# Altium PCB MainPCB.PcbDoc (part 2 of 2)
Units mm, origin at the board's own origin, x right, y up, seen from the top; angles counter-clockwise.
Board outline 105.16 x 70.61 mm, 2 copper layers (Top Layer, Bottom Layer); 130 components, 114 nets, 556 pads, 141 vias.
Unrouted connection lines stored in the file: 1.
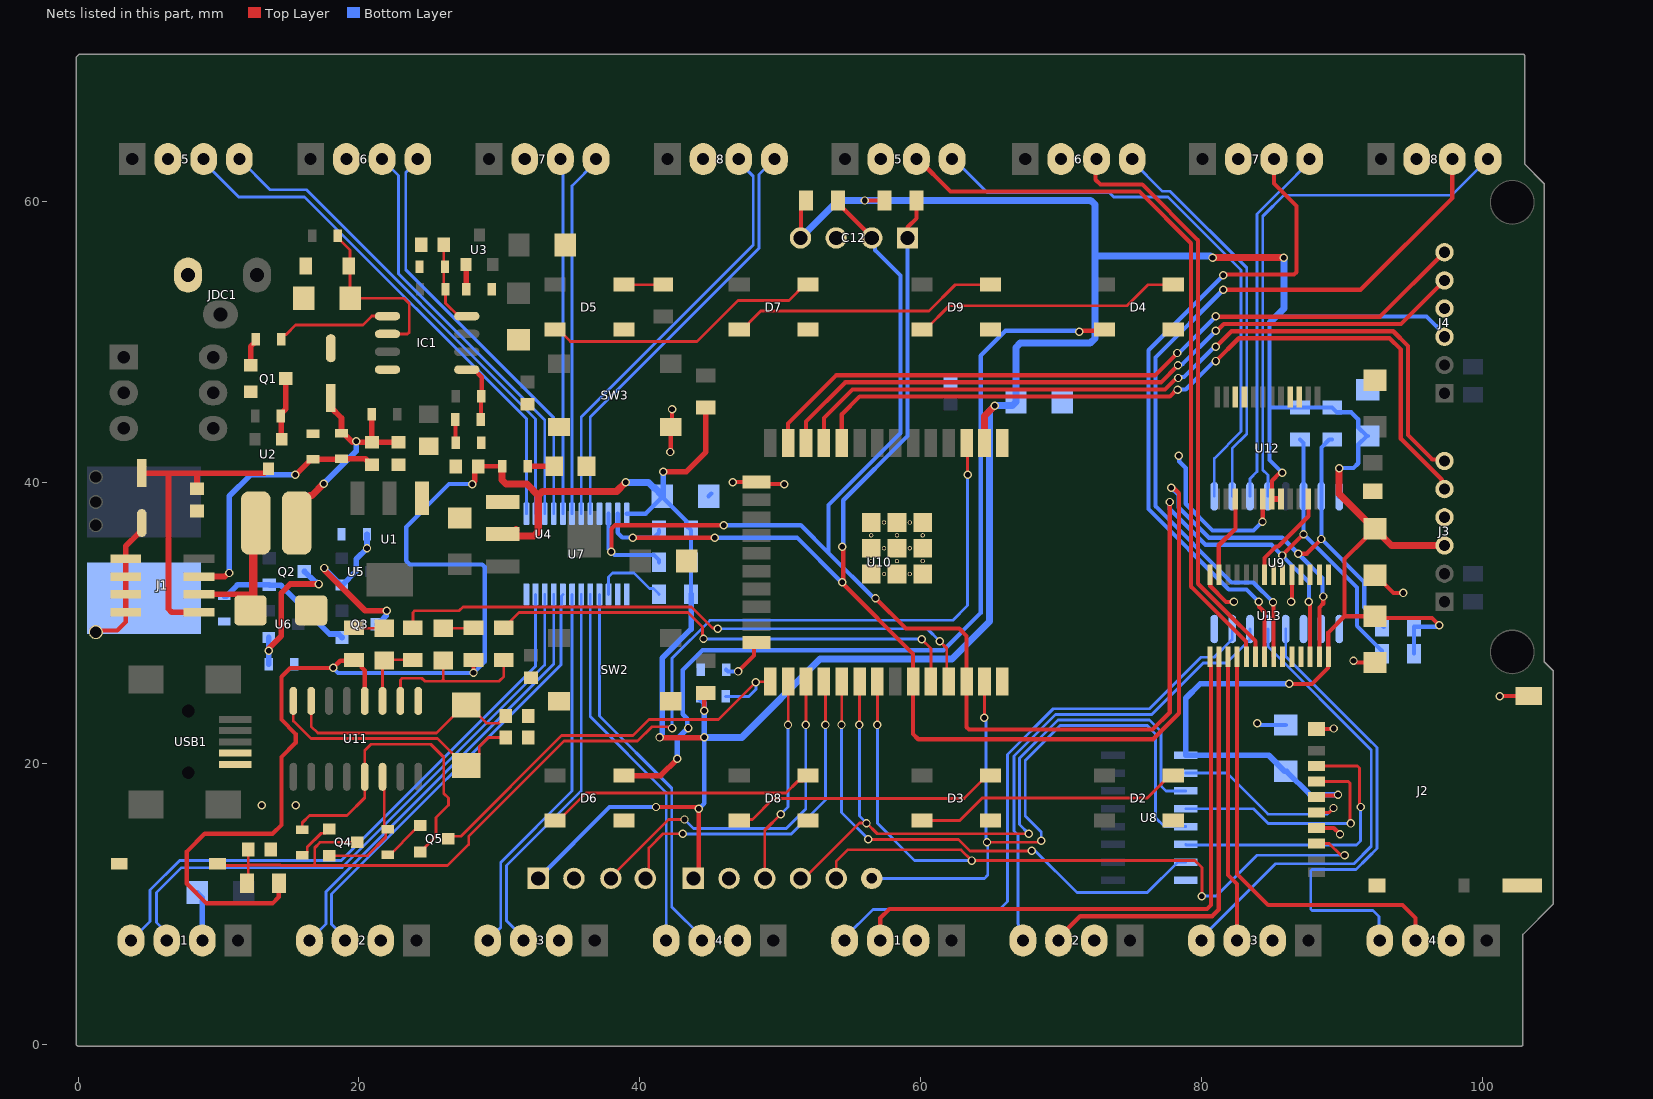
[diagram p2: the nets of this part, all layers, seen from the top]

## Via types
v1: diameter 0.6, hole 0.4, Top Layer to Bottom Layer, tented both sides, 141 vias

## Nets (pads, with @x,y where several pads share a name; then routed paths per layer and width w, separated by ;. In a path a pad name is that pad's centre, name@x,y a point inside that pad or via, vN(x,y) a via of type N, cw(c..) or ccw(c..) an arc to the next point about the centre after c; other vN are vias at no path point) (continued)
DTR_CH340: Q5.2 R29.1 U11.13 | length 23
  Top Layer w0.2: R29.1@15.965,15.266 15.965,15.774 16.473,16.282 19.14,16.282 20.41,17.552 U11.13@20.41,19.043 20.41,20.918 20.854,21.362 25.109,21.362 26.035,20.436 26.035,17.867 26.381,17.521 26.381,17.023 25.49,16.132 25.49,14.808 24.713,14.031 24.713,13.981 24.413,13.681 Q5.2@24.363,13.681
EN: Cx9.2 Q4.3 R28.1 SW4.1 U10.3 | length 83
  Top Layer w0.2: SW4.1@9.94,12.853 10.067,12.726 12.117,12.726 ; R28.1@12.028,11.456 12.117,11.545 12.117,12.774 ; Cx9.2@12.117,13.869 12.117,12.774 ; Q4.3@19.886,14.377 17.235,14.377 16.854,13.996 16.854,12.843 16.737,12.726 ; v1(42.291,22.514) 42.214,22.591 41.989,22.591 41.974,22.606 40.859,22.606 39.835,21.582 34.594,21.582 27.813,14.801 27.813,14.224 26.315,12.726 16.737,12.726 ; U10.3@63.262,42.816 63.336,42.742 v1(63.336,40.539) ; 12.117,12.774 14.403,12.774 14.451,12.726 16.737,12.726
  Bottom Layer w0.2: v1(42.291,22.514) 42.291,27.487 44.986,30.182 62.273,30.182 63.336,31.245 v1(63.336,40.539)
EN_POWER_BAT: IC1.1 R1.2 | length 8.3
  Top Layer w0.2: R1.2@14.479,50.191 14.479,50.341 14.679,50.541 14.829,50.541 15.495,51.207 20.283,51.207 20.918,51.842 IC1.1@22.03,51.842
GND: 1.2 2.2 3.2 4.2 5.2 6.2 7.2 8.2 -.1 BZT?.1 C1.1 C2.2 C3.2 C4.2 C5.2 C6.2 C7.2 C8.2 C9.1 C10.1 C11.1 C12.3 C13.1 C14.2 C15.2 C16.1 C17.2 C18.1 C19.1 Cx2.1 Cx3.1 Cx4.1 Cx5.1 Cx6.1 Cx7.1 Cx8.1 Cx9.1 Cx10.1 D1.A D2.3 D3.3 D4.3 D5.3 D6.3 D7.3 D8.3 D9.3 IC1.4 J1.5 J1.6 J1.7 J1.8 J2.6 J2.P1 J2.P2 J2.P3 J2.P4 J3.4 J4.4 JDC1.2 LED1.2 pad.5 pad.10 pad.17 Q1.1 R3.1 R7.1 R8.1 R9.1 R10.1 R12.2 R16.2 R27.1 SW2.1 SW2.4 SW3.1 SW3.4 SW4.2 U1.1 U4.1 U7.1 U7.2 U7.12 U7.21 U8.8 U9.1 U9.2 U9.3 U9.8 U10.1 U10.15 U10.38 U10.39_1 U10.39_2 U10.39_3 U10.39_4 U10.39_5 U10.39_6 U10.39_7 U10.39_8 U10.39_9 U10.39_10 U10.39_11 U10.39_12 U10.39_13 U10.39_14 U10.39_15 U10.39_16 U10.39_17 U10.39_18 U10.39_19 U10.39_20 U10.39_21 U11.1 U12.3 U12.4 U12.9 U12.10 U12.18 U13.1 U13.2 U13.3 U13.4 U13.5 U13.14 U13.23 U13.24 U13.25 USB1.4 USB1.5 | length 49.4
  Top Layer w0.3: pad.17@1.27,29.337 1.397,29.464 2.794,29.464 3.399,30.069 J1.8@3.399,30.76 ; v1(42.164,42.164) 42.202,42.202 SW3.1@42.202,43.942 42.291,44.031 v1(42.291,45.212) ; v1(46.609,40.005) 46.635,40.031 U10.15@48.292,40.031 48.445,39.878 v1(50.292,39.878) ; U13.14@80.583,33.427 80.61,33.399 80.61,32.625 81.739,31.496 v1(82.296,31.496) ; v1(84.328,37.211) 84.347,37.23 U12.18@84.347,38.819 ; v1(86.36,31.496) 86.425,31.561 U13.5@86.425,33.427 ; J2.6@88.179,15.403 89.404,15.403 v1(89.848,14.959) ; J2.P4@88.179,22.453 89.382,22.453 v1(89.408,22.479) ; v1(90.805,27.305) 90.932,27.178 C18.1@92.329,27.178 ; C16.1@92.329,33.401 92.392,33.401 93.662,32.131 v1(94.361,32.131) ; v1(101.219,24.765) 101.257,24.803 J2.P3@103.279,24.803
  Top Layer w0.4: J1.8@3.399,30.76 J1.7@3.399,32.03 J1.6@3.399,33.3 J1.5@3.399,34.57 3.399,35.47 4.332,36.403 4.396,36.403 4.535,36.541 C3.2@4.535,37.11
  Top Layer w0.6: U1.1@24.488,38.867 U1.1@24.488,39.567
  Bottom Layer w0.3: C11.1@44.896,39.015 C11.1@45.085,39.204 ; v1(78.359,41.91) 78.399,41.87 78.399,41.489 78.867,41.021 78.867,38.481 80.772,36.576 83.693,36.576 v1(84.328,37.211) ; v1(83.947,22.86) 84.074,22.733 C9.1@85.979,22.733
  Bottom Layer w0.4: C5.2@8.484,10.795 8.853,10.426 1.2@8.853,7.392
  other v1: 13.081,17.018 15.494,17.018
GPIO_0: Q5.3 R26.1 U10.25 | length 30.4
  Top Layer w0.2: Q5.3@26.363,14.631 26.536,14.804 27.25,14.804 34.428,21.982 39.508,21.982 40.64,23.114 45.593,23.114 v1(48.26,25.781) ; v1@48.26,25.816 U10.25@49.292,25.816
  Bottom Layer w0.2: R26.1@46.101,24.765 47.752,24.765 48.26,25.273 v1(48.26,25.781)
GPIO_2: R27.2 U10.24 | length 3.5
  Top Layer w0.3: v1(46.99,26.543) 48.133,27.686 48.133,28.442 U10.24@48.292,28.601
  Bottom Layer w0.3: R27.2@46.139,26.67 46.266,26.543 v1(46.99,26.543)
HAL_CHA_M1: J3.5 U10.10 | length 55.5
  Top Layer w0.3: U10.10@54.372,42.816 54.372,44.847 55.65,46.125 77.73,46.125 78.199,46.594 v1(78.28,46.594) ; v1(81.011,48.641) 82.636,50.266 93.371,50.266 94.177,49.46 94.177,43.11 97.089,40.198 97.089,39.716 J3.5@97.282,39.523
  Bottom Layer w0.3: v1(78.28,46.594) 78.295,46.609 78.867,46.609 v1@80.899,48.641
HAL_CHA_M2: J4.5 U10.12 | length 51.1
  Top Layer w0.3: U10.12@51.832,42.816 51.832,44.339 54.618,47.125 77.097,47.125 v1(78.312,48.34) ; v1(81.011,50.8) 81.092,50.8 81.574,51.282 94.183,51.282 J4.5@97.282,54.381
  Bottom Layer w0.3: v1(78.312,48.34) 78.37,48.398 78.608,48.398 v1(81.011,50.8)
HAL_CHB_M1: J3.6 U10.11 | length 56.1
  Top Layer w0.3: U10.11@53.102,42.816 53.102,44.593 55.134,46.625 77.392,46.625 78.203,47.436 v1(78.327,47.436) ; v1(81.011,49.657) 82.12,50.766 93.633,50.766 94.677,49.722 94.677,43.372 96.42,41.629 97.182,41.629 J3.6@97.282,41.529
  Bottom Layer w0.3: v1@78.265,47.498 78.74,47.498 80.749,49.507 80.78,49.507 80.899,49.626 v1@80.899,49.657 ; v1@78.27,47.493 v1(78.327,47.436)
HAL_CHB_M2: J4.6 U10.13 | length 53.2
  Top Layer w0.3: U10.13@50.562,42.816 50.546,42.832 50.546,44.196 53.975,47.625 76.678,47.625 v1(78.265,49.213) ; v1(81.011,51.831) 81.041,51.801 92.696,51.801 J4.6@97.282,56.387
  Bottom Layer w0.3: v1(78.265,49.213) 78.392,49.213 v1(81.011,51.831)
MCU_RX: R34.1 U10.34 | length 34.7
  Top Layer w0.2: R34.1@30.316,29.655 31.395,30.734 43.434,30.734 44.45,29.718 44.45,28.956 v1(44.529,28.877) ; v1(60.071,28.829) 60.071,28.816 60.722,28.165 U10.34@60.722,25.816
  Bottom Layer w0.2: v1(44.529,28.877) 44.553,28.853 60.047,28.853 v1(60.071,28.829)
MCU_TX: R33.1 U10.35 | length 42.9
  Top Layer w0.2: R33.1@23.839,29.655 23.839,30.744 23.956,30.861 27.13,30.861 27.403,31.134 43.669,31.134 45.164,29.639 45.499,29.639 v1(45.556,29.582) ; v1(61.341,28.702) 61.849,28.194 61.849,25.959 U10.35@61.992,25.816
  Bottom Layer w0.2: v1(45.556,29.582) 60.461,29.582 v1(61.341,28.702)
NetBZT?_2: BZT?.2 C8.1 IC1.2 R15.1 | length 12.8
  Top Layer w0.2: R15.1@18.505,57.557 18.505,57.407 19.369,56.544 C8.1@19.369,53.112 23.204,53.112 23.585,52.731 23.585,50.689 23.468,50.572 IC1.2@22.03,50.572
NetC3_1: C3.1 Cx3.2 J1.1 U2.3 | length 22.3
  Top Layer w0.4: C3.1@4.535,40.666 6.44,40.666 ; Cx3.2@8.472,39.561 8.472,40.539 8.599,40.666 ; J1.1@8.599,30.76 6.674,30.76 6.44,30.994 6.44,40.666 ; U2.3@13.552,40.963 13.552,40.913 13.352,40.713 13.302,40.713 13.255,40.666 8.599,40.666 ; 6.44,40.666 8.599,40.666
NetC4_1: C4.1 Cx1.1 Cx2.2 L1.2 R4.2 R5.1 | length 16.6
  Top Layer w0.4: C4.1@17.997,46 17.997,45.35 18.759,44.588 R4.2@18.759,43.498 18.909,43.498 v1@19.544,42.863 ; v1@19.812,42.863 Cx1.1@20.918,42.863 ; R5.1@20.918,44.857 Cx1.1@20.918,42.863 ; Cx2.2@22.823,42.863 Cx1.1@20.918,42.863
  Top Layer w0.5: L1.2@15.563,37.11 15.563,38.161 16.472,39.071 16.656,39.071 v1(17.489,39.904)
  Bottom Layer w0.4: v1(17.489,39.904) 19.812,42.227 v1(19.812,42.926)
NetCx1_2: Cx1.2 J1.3 R3.2 R4.1 | length 19.2
  Top Layer w0.4: J1.3@8.599,33.3 10.45,33.3 10.704,33.554 v1(10.758,33.554) ; v1(15.457,40.539) 15.472,40.539 16.577,41.644 R3.2@16.727,41.644 16.746,41.663 18.74,41.663 R4.1@18.759,41.682 20.449,41.682 20.868,41.263 Cx1.2@20.918,41.263
  Bottom Layer w0.4: v1(10.758,33.554) 10.758,39.015 12.282,40.539 v1(15.457,40.539)
NetCx5_2: Cx5.2 IC1.8 R11.2 R12.1 | length 6.1
  Top Layer w0.2: Cx5.2@26.036,56.922 26.036,55.353 26.036,53.874 R11.2@26.163,53.747 26.163,52.759 27.08,51.842 IC1.8@27.68,51.842
NetD1_C: D1.C J1.2 L1.1 | length 10.3
  Top Layer w0.4: J1.2@8.599,32.03 12.371,32.03 12.472,32.131
  Top Layer w0.6: D1.C@12.281,30.887 12.472,31.078 12.472,32.131 12.472,36.919 L1.1@12.663,37.11
NetD5_4: D5.4 R37.2 | length 2.8
  Top Layer w0.2: D5.4@38.862,54.076 41.63,54.076 R37.2@41.656,54.102
NetIC1_5: IC1.5 R13.2 R14.1 | length 4.3
  Top Layer w0.3: IC1.5@27.68,48.032 28.199,48.032 28.743,47.488 28.743,46.168 R13.2@28.703,46.127 28.684,46.108 28.684,44.495 R14.1@28.665,44.476
NetLabel438: U13.6
NetLabel439: U13.7
NetLED1_1: LED1.1 R6.1 | length 1.9
  Top Layer w0.4: R6.1@32.004,41.148 LED1.1@33.909,41.148
NetLED2_1: LD2.1 R30.1 | length 2.2
  Top Layer w0.2: R30.1@19.648,29.655 19.686,29.617 LD2.1@21.807,29.617
NetLED3_1: LD3.1 R31.1 | length 2.2
  Top Layer w0.2: LD3.1@25.998,29.617 28.119,29.617 R31.1@28.157,29.655
NetQ1_2: Q1.2 R2.1 U2.1 | length 4.5
  Top Layer w0.4: U2.1@14.502,43.063 14.472,43.093 14.472,44.7 R2.1@14.441,44.73 14.441,44.88 14.787,45.226 Q1.2@14.787,47.397
NetQ1_3: Q1.3 R1.1 | length 2
  Top Layer w0.4: Q1.3@12.287,48.347 12.287,49.665 12.663,50.041 R1.1@12.663,50.191
NetQ4_1: Q4.1 R29.2 | length 2.9
  Top Layer w0.2: R29.2@15.965,13.45 16.115,13.45 16.315,13.65 16.315,14.023 17.319,15.027 17.586,15.027 Q4.1@17.886,15.327
NetQ5_1: Q5.1 R32.1 | length 3.2
  Top Layer w0.2: R32.1@22.061,13.488 22.211,13.488 24.004,15.281 24.063,15.281 Q5.1@24.363,15.581
NetR7_2: R7.2 U3.1 | length 1.8
  Top Layer w0.4: U3.1@27.625,55.515 27.637,55.503 27.637,53.758 R7.2@27.648,53.747
NetR14_2: R14.2 R16.1 | length 1.7
  Top Layer w0.3: R14.2@26.849,44.476 26.868,44.457 26.868,42.844 R16.1@26.887,42.825
NetR17_1: R17.1 U7.3 | length 5.6
  Bottom Layer w0.2: U7.3@37.772,32.03 37.772,33.263 38.063,33.554 39.587,33.554 40.682,32.459 40.965,32.459 41.365,32.059 R17.1@41.365,32.03
OP1: 1.4@54.573,7.392 U9.7 | length 43.5
  Bottom Layer w0.2: 1.4@54.573,7.392 54.573,7.583 56.591,9.601 65.608,9.601 66.167,10.16 66.167,20.62 69.431,23.884 76.277,23.884 79.943,27.55 80.895,27.55 82.169,28.824 U9.7@82.169,29.565
OP2: 2.4@67.273,7.392 U9.6 | length 34.4
  Bottom Layer w0.2: 2.4@67.273,7.392 66.947,7.718 66.947,8.534 66.929,8.552 66.929,14.899 66.637,15.191 66.637,20.524 69.597,23.484 76.443,23.484 80.109,27.15 81.765,27.15 83.439,28.824 U9.6@83.439,29.565
OP3: 3.4@79.973,7.392 U9.5 | length 33.5
  Bottom Layer w0.2: 3.4@79.973,7.392 79.973,7.583 85.236,12.846 90.824,12.846 92.075,14.097 92.075,20.955 84.709,28.321 U9.5@84.709,29.565
OP4: 4.4@92.673,7.392 U9.4 | length 33.2
  Bottom Layer w0.2: U9.4@85.979,29.565 85.979,27.617 91.821,21.775 92.475,21.121 92.475,13.931 91.821,13.277 90.99,12.446 87.874,12.446 87.757,12.329 87.757,9.642 87.874,9.525 92.202,9.525 92.628,9.099 92.628,7.437 4.4@92.673,7.392
OP5: 5.4@62.23,63.018 U9.9 | length 40.9
  Bottom Layer w0.2: 5.4@62.284,63.272 62.284,63.082 64.744,60.621 73.444,60.621 73.74,60.325 77.597,60.325 82.804,55.118 82.804,43.619 80.899,41.714 U9.9@80.899,39.015
OP6: 6.4@75.057,63.018 U9.10 | length 28.3
  Bottom Layer w0.2: 6.4@74.984,63.145 74.984,62.955 77.213,60.725 77.763,60.725 83.204,55.284 83.204,43.453 82.169,42.418 U9.10@82.169,39.015
OP7: 7.4@87.684,63.018 U9.11 | length 25.8
  Bottom Layer w0.2: U9.11@83.439,39.015 83.439,40.259 83.947,40.767 83.947,59.113 85.686,60.852 85.708,60.852 87.684,62.828 7.4@87.684,63.018
OP8: 8.4@100.384,63.018 U9.12 | length 37.8
  Bottom Layer w0.2: U9.12@84.709,39.015 84.709,40.532 84.347,40.894 84.347,58.947 85.852,60.452 97.818,60.452 8.4@100.384,63.018
OUT_1: D5.2 D7.4 | length 20
  Top Layer w0.2: D5.2@33.962,50.876 34.212,50.876 35.05,50.038 44.069,50.038 46.99,52.959 50.607,52.959 51.724,54.076 D7.4@51.974,54.076
OUT_2: D7.2 D9.4 | length 19.2
  Top Layer w0.2: D7.2@47.074,50.876 47.324,50.876 47.724,51.276 47.724,51.318 47.841,51.435 48.603,52.197 60.579,52.197 62.458,54.076 D9.4@64.974,54.076
OUT_3: D4.4 D9.2 | length 19.2
  Top Layer w0.2: D9.2@60.074,50.876 60.324,50.876 62.026,52.578 74.676,52.578 76.174,54.076 D4.4@77.974,54.076
OUT_4: D4.2 D6.4 | length 62
  Top Layer w0.3: v1(71.288,50.714) 71.374,50.8 72.998,50.8 D4.2@73.074,50.876
  Top Layer w0.4: D6.4@38.862,19.126 41.478,19.126 v1(42.672,20.32)
  Bottom Layer w0.3: v1(43.434,22.514) 43.377,22.571 43.377,23.171 43.053,23.495 43.053,26.645 44.46,28.052 61.61,28.052 64.262,30.704 64.262,49.022 66.04,50.8 70.99,50.8 71.019,50.772 71.231,50.772 v1(71.288,50.714)
  Bottom Layer w0.4: v1(42.672,20.32) 42.672,21.752 v1(43.434,22.514)
OUT_5: D6.2 D8.4 | length 19.3
  Top Layer w0.2: D6.2@33.962,15.926 34.212,15.926 36.177,17.891 50.403,17.891 51.238,18.726 51.574,18.726 D8.4@51.974,19.126
OUT_6: D3.4 D8.2 | length 19.2
  Top Layer w0.2: D8.2@47.074,15.926 47.151,16.003 48.007,16.003 49.495,17.491 63.089,17.491 64.724,19.126 D3.4@64.974,19.126
OUT_7: D2.4 D3.2 | length 19.2
  Top Layer w0.2: D3.2@60.074,15.926 62.773,15.926 64.373,17.526 76.124,17.526 77.724,19.126 D2.4@77.974,19.126
PWM_A: U12.23 U13.8 | length 6.8
  Top Layer w0.3: U13.8@84.469,33.427 84.469,34.614 85.299,35.444 85.453,35.444 87.597,37.588 U12.23@87.597,38.819
PWM_B: U12.15 U13.13 | length 5.9
  Top Layer w0.3: U13.13@81.218,33.427 81.218,35.527 82.397,36.706 U12.15@82.397,38.819
RST_CH340: Q4.2 R32.2 U11.14 | length 9.1
  Top Layer w0.2: Q4.2@17.886,13.427 20.603,13.427 21.911,14.735 R32.2@21.911,15.304 ; U11.14@21.68,19.043 21.68,18.223 21.807,18.096 21.807,15.408 R32.2@21.911,15.304 ; R32.2@22.061,15.304 R32.2@21.911,15.304
S1: 1.3@57.113,7.392 U13.15 | length 43.2
  Top Layer w0.3: 1.3@57.113,7.392 57.113,8.985 57.76,9.632 80.371,9.632 80.66,9.921 80.66,26.949 80.61,26.998 80.61,27.557 U13.15@80.583,27.585
S2: 2.3@69.813,7.392 U13.16 | length 30.4
  Top Layer w0.3: 2.3@69.813,7.392 69.813,7.583 71.349,9.118 80.746,9.118 81.218,9.59 U13.16@81.218,27.585
S3: 3.3@82.513,7.392 U13.17 | length 20.5
  Top Layer w0.3: U13.17@81.878,27.585 81.878,12.052 82.513,11.417 3.3@82.513,7.392
S4: 4.3@95.213,7.392 U13.18 | length 31.1
  Top Layer w0.3: U13.18@82.513,27.585 82.513,12.124 84.731,9.906 94.292,9.906 95.213,8.985 4.3@95.213,7.392
S5: 5.3@59.69,63.018 U13.19 | length 53.3
  Top Layer w0.3: 5.3@59.744,63.272 59.744,63.082 62.119,60.706 75.565,60.706 79.241,57.03 79.241,32.58 83.146,28.675 83.146,27.613 U13.19@83.173,27.585
S6: 6.3@72.517,63.018 U13.20 | length 42
  Top Layer w0.3: 6.3@72.444,63.145 72.444,61.552 72.79,61.206 75.772,61.206 79.741,57.237 79.741,32.787 81.749,30.779 83.829,28.7 83.829,27.59 U13.20@83.834,27.585
S7: 7.3@85.144,63.018 U13.21 | length 47.5
  Top Layer w0.3: v1(81.534,54.737) 81.591,54.794 86.565,54.794 86.741,54.97 86.741,59.69 85.144,61.287 7.3@85.144,63.018 ; v1(84.074,31.496) 84.074,31.157 84.469,30.762 U13.21@84.469,27.585
  Bottom Layer w0.3: v1(81.534,54.737) 76.208,49.411 76.208,38.102 81.925,32.385 83.185,32.385 v1(84.074,31.496)
S8: 8.3@97.844,63.018 U13.22 | length 54.3
  Top Layer w0.3: v1(81.534,53.721) 91.313,53.721 97.844,60.252 8.3@97.844,63.018 ; v1(85.075,31.481) 85.102,31.454 85.102,27.612 U13.22@85.129,27.585
  Bottom Layer w0.3: v1(81.534,53.721) 76.708,48.895 76.708,38.309 82.132,32.885 83.671,32.885 v1(85.075,31.481)
SCL: C12.2 R18.1 R21.1 R22.1 R36.1 U7.22 U9.14 U10.36 U13.26 | length 139.6
  Top Layer w0.3: v1(37.973,35.052) 37.973,36.703 38.227,36.957 v1(45.974,36.957) ; R22.1@54.102,60.071 54.102,59.873 56.515,57.46 C12.2@56.515,57.404 ; v1(56.777,31.75) 58.936,29.591 62.738,29.591 63.262,29.067 U10.36@63.262,25.816 63.262,22.576 63.438,22.401 76.503,22.401 77.724,23.622 77.724,38.601 v1(77.717,38.608) ; v1(85.725,34.798) v1@87.249,36.321 ; v1(87.63,31.496) 87.72,31.406 U13.26@87.72,27.585
  Bottom Layer w0.3: v1@37.772,35.253 U7.22@37.772,37.77 ; 38.201,34.824 41.015,34.824 41.365,34.474 R18.1@41.365,34.316 ; v1(45.974,36.957) 51.45,36.957 53.431,34.976 ; C12.2@56.515,57.404 56.748,57.171 56.748,56.536 58.547,54.737 58.547,43.506 53.431,38.39 53.431,34.976 ; v1(56.777,31.75) 56.657,31.75 53.431,34.976 ; v1(77.717,38.608) 77.724,38.601 77.724,38.1 80.264,35.56 84.963,35.56 v1(85.725,34.798) 87.63,32.893 v1(87.63,31.496) ; R21.1@86.995,43.053 87.249,42.799 U9.14@87.249,39.015 v1(87.249,36.321) 91.059,32.511 91.059,29.789 92.837,28.011 R36.1@92.837,27.813
SCL_0: 4.4@41.873,7.392 U7.5 | length 26.9
  Bottom Layer w0.2: U7.5@36.472,32.03 36.472,23.334 41.873,17.933 4.4@41.873,7.392
SCL_1: 3.4@29.173,7.392 U7.7 | length 27.1
  Bottom Layer w0.2: 3.4@29.173,7.392 30.099,8.318 30.099,12.954 35.172,18.027 U7.7@35.172,32.03
SCL_2: 2.4@16.473,7.392 U7.9 | length 31.8
  Bottom Layer w0.2: 2.4@16.473,7.392 17.653,8.572 17.653,10.862 33.872,27.081 U7.9@33.872,32.03
SCL_3: 1.4@3.773,7.392 U7.11 | length 43.3
  Bottom Layer w0.2: 1.4@3.773,7.392 5.128,8.747 5.128,10.97 7.239,13.081 18.741,13.081 32.572,26.912 U7.11@32.572,32.03
SCL_4: 5.4@11.484,63.018 U7.14 | length 35.5
  Bottom Layer w0.2: 5.4@11.484,63.018 13.669,60.833 16.256,60.833 32.572,44.517 U7.14@32.572,37.77
SCL_5: 6.4@24.184,63.018 U7.16 | length 30
  Bottom Layer w0.2: 6.4@24.184,63.018 24.184,62.928 23.331,62.075 23.331,55.144 33.872,44.603 U7.16@33.872,37.77
SCL_6: 7.4@36.884,63.018 U7.18 | length 26
  Bottom Layer w0.2: U7.18@35.172,37.77 35.172,61.116 36.884,62.828 7.4@36.884,63.018
SCL_7: 8.4@49.584,63.018 U7.20 | length 30.7
  Bottom Layer w0.2: U7.20@36.472,37.77 36.472,44.663 48.477,56.668 48.477,61.911 8.4@49.584,63.018
SD_CLK: J2.5 U8.2 | length 13.2
  Top Layer w0.2: J2.5@88.179,16.503 88.182,16.506 89.079,16.506 89.381,16.808 v1(89.381,16.823)
  Bottom Layer w0.2: U8.2@78.867,19.304 81.788,19.304 84.709,16.383 88.94,16.383 v1(89.381,16.823)
SD_CS: J2.2 U8.6 | length 20.9
  Top Layer w0.2: J2.2@88.179,19.803 91.1,19.803 91.227,19.676 91.227,16.977 v1(91.313,16.891)
  Bottom Layer w0.2: U8.6@78.867,14.224 78.902,14.189 91.024,14.189 91.313,14.478 v1(91.313,16.891)
SD_MOSI: J2.3 U8.4 | length 17.5
  Top Layer w0.2: J2.3@88.179,18.703 90.434,18.703 90.551,18.586 90.551,15.78 v1(90.61,15.721)
  Bottom Layer w0.2: U8.4@78.867,16.764 83.693,16.764 84.736,15.721 v1(90.61,15.721)
SDA: C12.1 R19.1 R20.1 R23.1 R35.1 U7.23 U9.15 U10.33 U13.27 | length 136.8
  Top Layer w0.3: v1(39.497,36.068) v1(45.339,36.068) ; v1@54.483,35.433 54.483,32.766 59.452,27.797 U10.33@59.452,25.816 59.452,22.082 59.817,21.717 76.526,21.717 78.374,23.565 78.374,39.228 77.978,39.624 v1(77.836,39.624) ; C12.1@59.055,57.404 59.055,58.166 59.69,58.801 R19.1@59.69,60.071 ; v1(86.87,34.925) 87.474,34.925 v1(88.519,35.97) ; U13.27@88.408,27.557 U13.27@88.38,27.585 88.38,31.103 88.646,31.369 v1(88.646,31.877)
  Bottom Layer w0.3: U7.23@38.422,37.77 38.422,36.411 38.747,36.086 v1@39.489,36.086 ; v1@39.523,36.068 41.015,36.068 41.365,36.418 R23.1@41.365,36.602 ; v1(45.339,36.068) 51.181,36.068 54.356,32.893 v1(54.419,32.893) ; v1@54.483,35.433 54.483,38.735 59.055,43.307 C12.1@59.055,57.404 ; v1(77.836,39.624) 78.367,39.093 78.367,38.219 80.526,36.06 85.735,36.06 v1(86.87,34.925) 88.606,33.189 88.606,31.917 v1(88.646,31.877) ; R20.1@89.281,43.053 89.083,43.053 88.519,42.489 U9.15@88.519,39.015 v1(88.519,35.97) 91.567,32.922 91.567,31.115 R35.1@92.964,29.718
  other v1: 54.419,35.433
SDA_0: 4.3@44.413,7.392 U7.4 | length 27.7
  Bottom Layer w0.2: U7.4@37.122,32.03 37.122,23.377 42.273,18.226 42.273,9.786 44.413,7.646 4.3@44.413,7.392
SDA_1: 3.3@31.713,7.392 U7.6 | length 27.3
  Bottom Layer w0.2: 3.3@31.713,7.392 31.713,7.583 30.499,8.797 30.499,12.719 35.822,18.042 U7.6@35.822,32.03
SDA_2: 2.3@19.013,7.392 U7.8 | length 31.9
  Bottom Layer w0.2: 2.3@19.013,7.392 19.013,7.583 18.053,8.543 18.053,10.696 34.377,27.02 34.377,31.228 34.417,31.268 34.417,31.925 U7.8@34.522,32.03
SDA_3: 1.3@6.313,7.392 U7.10 | length 43.1
  Bottom Layer w0.2: 1.3@6.313,7.392 6.313,7.954 5.588,8.679 5.588,10.795 7.366,12.573 18.799,12.573 33.222,26.996 U7.10@33.222,32.03
SDA_4: 5.3@8.944,63.018 U7.13 | length 37.5
  Bottom Layer w0.2: 5.3@8.944,63.018 8.944,62.828 11.446,60.325 16.129,60.325 31.922,44.532 U7.13@31.922,37.77
SDA_5: 6.3@21.644,63.018 U7.15 | length 30
  Bottom Layer w0.2: 6.3@21.644,63.018 22.823,61.839 22.823,54.857 33.222,44.458 U7.15@33.222,37.77
SDA_6: 7.3@34.344,63.018 U7.17 | length 25.3
  Bottom Layer w0.2: 7.3@34.344,63.018 34.522,62.84 U7.17@34.522,37.77
SDA_7: 8.3@47.044,63.018 U7.19 | length 30.8
  Bottom Layer w0.2: U7.19@35.822,37.77 35.822,44.636 48.077,56.891 48.077,61.794 47.044,62.828 8.3@47.044,63.018
SPI_CLK: pad.3 U8.3 U10.30 | length 51.6
  Top Layer w0.2: pad.3@51.435,11.811 51.689,11.811 55.626,15.748 v1(56.134,15.748) 56.896,14.986 v1(67.691,14.986) ; v1@55.626,22.606 55.642,22.622 U10.30@55.642,25.816
  Bottom Layer w0.2: v1(55.626,22.733) 55.626,16.256 v1(56.134,15.748) ; v1(67.691,14.986) 67.037,15.64 67.037,20.359 69.762,23.084 76.288,23.084 77.108,22.264 77.108,18.396 77.47,18.034 U8.3@78.867,18.034
SPI_CS: U8.7 U10.29 | length 37.1
  Top Layer w0.2: v1(54.356,22.733) 54.372,22.749 U10.29@54.372,25.816 ; v1(56.261,14.605) 56.28,14.586 62.688,14.586 63.505,13.769 v1(67.892,13.769)
  Bottom Layer w0.2: v1(54.356,22.733) 54.356,16.51 v1(56.261,14.605) ; v1(67.892,13.769) 68.146,13.769 71.12,10.795 76.124,10.795 78.283,12.954 U8.7@78.867,12.954
SPI_CS_SREEN: pad.4 U10.26 | length 14.8
  Top Layer w0.2: pad.4@48.895,11.811 48.895,15.24 v1(50.038,16.383) ; v1@50.546,22.606 50.562,22.622 U10.26@50.562,25.816
  Bottom Layer w0.2: v1(50.038,16.383) 50.546,16.891 v1(50.546,22.733)
SPI_MISO: J2.7 pad.2 U10.31 | length 61.7
  Top Layer w0.2: pad.2@53.975,11.811 53.975,13.023 54.795,13.843 62.865,13.843 v1(63.627,13.081) 79.502,13.081 80.01,12.573 v1(80.01,10.548) ; v1(56.912,22.733) U10.31@56.912,25.816 ; J2.7@88.179,14.303 89.075,14.303 89.916,13.462 v1(90.17,13.462)
  Bottom Layer w0.2: v1(56.912,22.733) 56.912,15.732 59.563,13.081 v1(63.627,13.081) ; v1(80.01,10.548) 81.033,10.548 83.947,13.462 v1(90.17,13.462)
SPI_MOSI: pad.8 U8.5 U10.37 | length 51.3
  Top Layer w0.2: v1(64.516,23.241) 64.532,23.257 U10.37@64.532,25.816 ; v1(64.712,14.386) 68.485,14.386 v1(68.58,14.481)
  Bottom Layer w0.2: pad.8@56.515,11.811 64.526,11.811 64.77,12.055 64.77,14.328 64.643,14.455 64.643,23.006 64.516,23.133 v1(64.516,23.241) ; v1(68.58,14.481) 68.58,15.113 67.437,16.256 67.437,20.193 69.928,22.684 76.122,22.684 76.708,22.098 76.708,16.129 77.343,15.494 U8.5@78.867,15.494
TP: Q2.3 Q3.3 R8.2 | length 10.3
  Bottom Layer w0.4: R8.2@10.414,31.915 10.564,31.915 11.354,32.705 Q2.3@13.609,32.705 13.647,32.667 14.45,32.667 17.911,29.206 18.546,29.206 Q3.3@18.796,28.956
TP1: Q3.2 R9.2 U5.1 | length 13.2
  Top Layer w0.4: v1(17.526,33.909) 17.526,33.782 20.447,30.861 v1(21.971,30.861)
  Bottom Layer w0.4: v1(17.526,33.909) 17.526,33.9 18.721,32.705 U5.1@18.771,32.705 18.821,32.705 19.797,33.681 19.797,34.529 v1(20.574,35.306) R9.2@20.574,36.322 ; Q3.2@21.296,29.906 21.321,29.906 21.811,30.396 21.933,30.518 21.933,30.823 v1(21.971,30.861)
TP2: Q2.2 R10.2 U6.1 | length 10.7
  Top Layer w0.4: v1(13.587,28.006) 13.587,28.192 14.478,29.083 14.478,32.131 15.113,32.766 v1(17.145,32.766)
  Bottom Layer w0.4: U6.1@13.584,28.961 13.587,28.958 13.587,27.053 R10.2@13.589,27.051 ; Q2.2@16.109,33.655 16.134,33.655 16.896,32.893 17.018,32.893 v1(17.145,32.766)
U2_RX: pad.9 U10.27 | length 25.7
  Top Layer w0.2: pad.9@37.936,11.811 37.936,11.901 42.037,16.002 v1(43.18,16.002) ; v1@51.816,22.606 51.832,22.622 U10.27@51.832,25.816
  Bottom Layer w0.2: v1(43.18,16.002) 43.815,15.367 50.419,15.367 51.816,16.764 v1(51.816,22.733)
U2_TX: pad.7 U10.28 | length 24.9
  Top Layer w0.2: pad.7@40.386,11.811 40.639,12.064 40.639,13.969 41.656,14.986 v1(43.053,14.986) ; U10.28@53.102,25.816 53.213,25.705 v1(53.213,22.733) v1@53.213,22.606
  Bottom Layer w0.2: v1(43.053,14.986) 43.072,14.967 50.781,14.967 53.213,17.399 v1(53.213,22.733)
USB_RX: LD2.2 R33.2 U11.3 | length 5
  Top Layer w0.2: U11.3@21.68,24.443 21.68,27.204 LD2.2@21.807,27.331 21.845,27.369 R33.2@23.839,27.369
USB_TX: LD3.2 R34.2 U11.2 | length 11.9
  Top Layer w0.2: U11.2@22.95,24.443 22.95,25.934 23.077,26.061 24.474,26.061 24.693,25.842 26.09,25.842 ; LD3.2@25.998,27.331 25.998,25.969 25.98,25.952 26.09,25.842 ; R34.2@30.316,27.369 30.316,26.188 29.97,25.842 26.09,25.842
VCC: C9.2 C10.2 C11.2 C12.4 C13.2 C16.2 C18.2 Cx4.2 J2.4 J3.3 J4.3 pad.6 pad.11 R6.2 R17.2 R18.2 R19.2 R20.2 R21.2 R22.2 R23.2 R24.2 R25.2 R26.2 R28.2 R30.2 R31.2 R35.2 R36.2 U4.2 U7.24 U8.1 U9.16 U10.2 U11.4 U12.19 U12.20 U13.28 | length 366.5
  Top Layer w0.3: R28.2@14.314,11.456 14.293,11.435 14.293,10.483 13.843,10.033 9.144,10.033 7.747,11.43 7.747,13.716 9.017,14.986 13.843,14.986 14.478,15.621 14.478,20.447 15.494,21.463 15.494,22.098 14.478,23.114 14.478,26.162 15.113,26.797 v1(18.161,26.797) 18.669,27.305 19.782,27.305 19.846,27.369 20.197,27.019 20.197,26.821 20.41,26.607 U11.4@20.41,24.443 ; v1(28.157,26.442) R31.2@28.157,27.369 ; Cx4.2@28.486,41.148 R6.2@30.188,41.148 ; v1(41.148,16.891) 44.069,16.891 v1(44.196,16.764) 44.196,12.446 44.323,12.319 pad.6@43.815,11.811 ; v1(44.577,23.749) 44.577,24.892 R24.2@44.704,25.019 ; C12.4@51.435,57.404 51.466,57.435 51.466,59.721 R22.2@51.816,60.071 ; v1(56.007,60.071) R19.2@57.404,60.071 ; U12.19@84.997,38.819 84.997,40.124 85.575,40.702 v1(85.725,40.702) ; v1(86.233,25.654) 87.859,25.654 88.988,26.783 88.988,27.278 89.015,27.306 U13.28@89.015,27.585 89.015,29.314 90.17,30.468 ; J2.4@88.179,17.603 88.29,17.714 89.646,17.714 v1(89.703,17.771) ; C16.2@92.329,36.703 92.266,36.703 91.653,36.091 91.653,36.027 90.17,34.544 90.17,30.468 ; v1(96.901,29.845) 96.393,30.353 92.814,30.353 92.698,30.468 90.17,30.468
  Top Layer w0.4: v1(28.067,39.878) 28.067,39.932 28.236,40.101 28.236,40.898 Cx4.2@28.486,41.148 ; v1(41.402,21.844) 41.432,21.814 44.547,21.814 v1(44.586,21.853) ; v1(41.656,40.767) 43.307,40.767 44.704,42.164 R25.2@44.704,45.339 ; U12.19@84.997,38.819 U12.20@85.647,38.819
  Top Layer w0.5: R6.2@30.188,41.148 30.188,40.171 30.481,39.878 31.965,39.878 32.766,39.077 ; U4.2@30.247,36.322 30.947,36.322 31.197,36.572 U4.2@31.197,36.658 ; U4.2@30.947,36.195 32.473,36.195 32.766,36.488 32.766,39.077 ; v1(38.989,40.005) 38.354,39.37 33.059,39.37 32.766,39.077 ; U10.2@64.532,42.816 64.532,44.72 v1(65.278,45.466) ; v1(80.772,56.007) v1(85.852,56.007) ; v1(89.789,41.021) 89.789,39.179 C16.2@92.266,36.703 ; C16.2@92.329,36.703 92.392,36.703 92.905,36.191 92.905,36.127 93.522,35.51 J3.3@97.282,35.51
  Bottom Layer w0.3: v1(18.161,26.797) 18.516,26.442 v1(28.157,26.442) 28.956,27.241 28.956,33.987 28.78,34.163 23.622,34.163 23.368,34.417 23.368,36.83 26.416,39.878 v1(28.067,39.878) ; pad.11@32.766,11.811 37.846,16.891 v1(41.148,16.891) ; U7.24@39.072,37.77 40.412,37.77 C11.2@41.594,38.952 ; C11.2@41.594,39.015 C11.2@41.594,38.952 ; R17.2@43.651,32.03 R18.2@43.651,34.316 R23.2@43.651,36.602 43.301,36.952 43.301,37.244 C11.2@41.594,38.952 ; v1(44.196,16.764) 44.586,17.154 v1(44.586,21.853) ; 84.866,51.465 84.836,51.435 84.836,45.339 ; 85.278,51.816 96.012,51.816 97.282,50.546 J4.3@97.282,50.368 ; v1(85.725,40.702) 84.836,41.591 84.836,45.339 ; U9.16@89.789,39.756 v1(89.789,41.021) 90.805,41.021 91.145,41.361 91.145,42.695 C10.2@91.757,43.307 ; C10.2@91.821,43.307 C10.2@91.757,43.307 ; R36.2@95.123,27.813 R35.2@95.123,29.718 96.693,29.718 96.82,29.845 v1(96.901,29.845) ; 84.836,45.339 R21.2@86.995,45.339 R20.2@89.281,45.339 89.631,44.989 90.647,44.989 91.145,44.491 91.145,43.919 C10.2@91.757,43.307
  Bottom Layer w0.4: v1(41.402,21.844) 41.591,22.033 41.591,27.494 43.651,29.554 R17.2@43.651,32.03 ; C11.2@41.594,39.015 41.656,39.077 v1(41.656,40.767) ; R26.2@44.285,24.765 44.196,24.676 44.586,24.286 v1(44.586,21.853) ; v1(86.233,25.654) 79.883,25.654 78.867,24.638 U8.1@78.867,20.574 84.772,20.574 85.915,19.431 C9.2@85.979,19.431 86.042,19.431 87.702,17.771 v1(89.703,17.771) ; U9.16@89.789,39.015 U9.16@89.789,39.756
  Bottom Layer w0.5: v1(38.989,40.005) 40.604,40.005 41.018,39.591 41.082,39.591 41.594,39.079 C11.2@41.594,39.015 ; v1(44.586,21.853) 47.253,21.853 52.832,27.432 62.23,27.432 64.897,30.099 64.897,45.085 v1(65.278,45.466) 66.523,45.466 C13.2@66.777,45.72 66.777,49.618 67.069,49.911 72.046,49.911 72.39,50.255 72.39,56.134 ; C12.4@51.435,57.404 54.102,60.071 v1(56.007,60.071) 72.097,60.071 72.39,59.778 72.39,56.134 ; v1(80.772,56.007) 80.745,56.007 80.618,56.134 72.39,56.134 ; 84.897,51.435 85.278,51.816 85.852,52.39 v1(85.852,56.007)
XI: C14.1 U11.7 Y1.2 | length 17.5
  Top Layer w0.2: U11.7@16.6,24.443 16.6,22.632 17.073,22.159 20.193,22.159 20.196,22.162 25.528,22.162 27.522,24.156 27.776,24.156 29.072,22.86 29.984,22.86 30.442,23.318 C14.1@30.442,23.368
XO: C15.1 U11.8 Y1.1 | length 19
  Top Layer w0.2: U11.8@15.33,24.443 15.33,23.013 16.584,21.759 20.358,21.759 20.361,21.762 25.598,21.762 27.522,19.838 Y1.1@27.649,19.838 27.776,19.838 28.565,20.627 28.565,21.199 29.21,21.844 C15.1@30.442,21.844
pads on no net: D2.2 J1.4 J2.1 J2.8 J2.SWA J2.SWB JDC1.3 SW1.1 SW1.4 SW1.5 SW1.6 U1.4 U4.4 U8.9 U8.10 U8.11 U8.12 U8.13 U8.14 U8.15 U8.16 U9.13 U10.5 U10.6 U10.7 U10.9 U10.16 U10.17 U10.18 U10.19 U10.20 U10.21 U10.22 U10.32 U11.9 U11.10 U11.11 U11.12 U11.15 USB1.6 USB1.7 USB1.8 USB1.9 USB1.MH1 USB1.MH2
copper on no net: | length 0.2
  Top Layer w0.2: 55.642,42.816 55.753,42.927

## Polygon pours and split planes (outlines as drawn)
GND on Bottom Layer "Bottom Layer-No Net" (solid, pour order 0): 0,-0.127 cw(c0,0) -0.127,0 -0.127,70.231 cw(c0,70.231) -0.09,70.322 -0.09,70.321 0.037,70.448 0.036,70.448 cw(c0.127,70.358) 0.127,70.485 102.87,70.485 cw(c102.87,70.358) 102.997,70.358 102.997,62.664 104.357,61.304 104.357,61.305 cw(c104.267,61.214) 104.394,61.214 104.394,27.231 104.992,26.633 104.992,26.634 cw(c104.902,26.543) 105.029,26.543 105.029,10.033 cw(c104.902,10.033) 104.992,9.942 104.992,9.943 102.87,7.821 102.87,0.127 cw(c102.743,0.127) 102.853,0.064 cw(c102.743,0) 102.87,0 cw(c102.743,0) 102.743,-0.127
GND on Top Layer "Top Layer-No Net" (solid, remove dead copper, pour order 1): 0,-0.127 cw(c0,0) -0.127,0 -0.127,70.231 cw(c0,70.231) -0.09,70.322 -0.09,70.321 0.037,70.448 0.036,70.448 cw(c0.127,70.358) 0.127,70.485 102.87,70.485 cw(c102.87,70.358) 102.997,70.358 102.997,62.664 104.357,61.304 104.357,61.305 cw(c104.267,61.214) 104.394,61.214 104.394,27.231 104.992,26.633 104.992,26.634 cw(c104.902,26.543) 105.029,26.543 105.029,10.033 cw(c104.902,10.033) 104.992,9.942 104.992,9.943 102.87,7.821 102.87,0.127 cw(c102.743,0.127) 102.853,0.064 cw(c102.743,0) 102.87,0 cw(c102.743,0) 102.743,-0.127

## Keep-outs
Keep-Out Layer:
  lines w0.254: 0,28.956 0,69.088 0,70.231 0.127,70.358 102.87,70.358 102.87,62.611 104.267,61.214 104.267,27.178 104.902,26.543 104.902,10.033 102.743,7.874 102.743,7.493 102.743,0.127 ; 0,29.21 0,0 102.743,0

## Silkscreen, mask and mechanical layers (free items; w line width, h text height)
Top Overlay:
  lines w0.254: 1.524,6.223 1.524,9.144 51.689,9.144 51.816,9.017 51.816,6.35 ; 1.524,63.627 1.524,61.722 51.943,61.722 51.943,63.881 ; 52.451,9.017 102.362,9.017 102.362,6.604 ; 52.451,61.722 102.616,61.722 102.616,64.008
  text "SUNY ROBOT" at 49.774,45.144 h5
  text "+ - CS CLK SO SI" at 43.688,13.48 h1.52
  text "+- RX TX" at 33.274,13.335 h1.52
Bottom Overlay:
  lines w0.254: 2.286,8.128 2.286,13.208 3.048,13.208 31.496,13.208 31.496,10.16 46.99,10.16 ; 2.286,61.087 2.286,58.293 2.413,58.166 51.816,58.166 51.816,61.341 ; 46.736,10.16 51.562,10.16 51.816,9.906 51.816,8.89 ; 52.197,58.166 100.203,58.166 100.203,60.706 ; 52.451,9.144 52.451,10.16 57.531,10.16 60.198,10.16 60.198,12.7 101.727,12.7 101.981,12.446
  text "OUTPUT  D PWM - +" at 80.645,56.411 h2
  text "INPUT S2 S1 - +" at 33.401,55.401 h2.5
  text "INPUT + - S1 S2" at 30.099,9.935 h2.5
  text "OUTPUT + - PWM D" at 83.058,9.144 h2.5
